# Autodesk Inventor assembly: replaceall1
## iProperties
Author: Administrator
Created: 2001-01
Part Number: replaceall1
Document SubType Name: Assembly
Designer: Administrator
Control State: 0
Master: False
Checked Out: False
PropertySet Name: Design Tracking Control
Shininess: 0.0
PropertySet Name: _Private Model Information
Density: 0.0
Volumn: 0.0
Area: 0.0
PropertySet Name: Model Information
